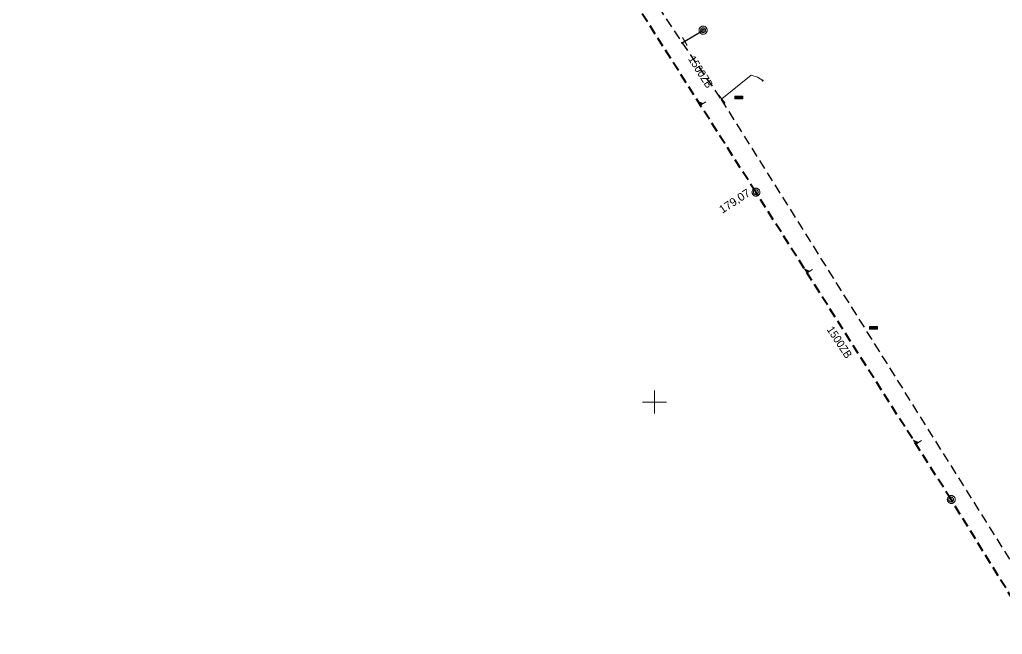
# Model space of a CAD drawing. Extents: x -740851 to -738888, y -1041382 to -1040235.
# Drawn here: x -739579.3 to -739456.5, y -1040929 to -1040852.2 of the extents above; entities that cross this region are included whole.
import ezdxf

# ---------------------------------------------------------------- set-up
doc = ezdxf.new("R2010")
doc.units = 0
doc.header["$LTSCALE"] = 0.4
doc.linetypes.add('MEDIUM_DASHED', pattern=[4.5, 3, -1.5])
for name, color, linetype, lineweight in [('1', 7, 'Continuous', 13), ('18', 7, 'Continuous', 13), ('38', 7, 'Continuous', 13), ('8', 7, 'Continuous', 13)]:
    doc.layers.add(name, color=color, linetype=linetype, lineweight=lineweight)

msp = doc.modelspace()

# ---------------------------------------------------------------- hatches: boundary and pattern name
at = {"layer": '18'}
for points in [[(-739489.96, -1040861.78), (-739489.96, -1040862.12), (-739488.96, -1040862.12), (-739488.96, -1040861.78)], [(-739473.14, -1040890.56), (-739473.14, -1040890.9), (-739472.14, -1040890.9), (-739472.14, -1040890.56)]]:
    msp.add_hatch(color=256, dxfattribs=at).paths.add_polyline_path(points)

# ---------------------------------------------------------------- linework, layer by layer
at = {"layer": '1'}
for p, q in [((-739500, -1040898.571), (-739500, -1040901.429)), ((-739500, -1040898.571), (-739500, -1040901.429)), ((-739501.48, -1040900), (-739498.48, -1040900)), ((-739501.48, -1040900), (-739498.48, -1040900))]:
    msp.add_line(p, q, dxfattribs=at)
at = {"layer": '18', "linetype": 'MEDIUM_DASHED', "lineweight": 40}
for p, q in [((-739487.34, -1040873.78), (-739504.725, -1040846.471)), ((-739462.93, -1040912.16), (-739487.34, -1040873.78)), ((-739433.4, -1040959.96), (-739462.93, -1040912.16))]:
    msp.add_line(p, q, dxfattribs=at)
at = {"layer": '18'}
for p, q in [((-739489.96, -1040861.78), (-739488.96, -1040862.12)), ((-739473.14, -1040890.56), (-739472.14, -1040890.9))]:
    msp.add_line(p, q, dxfattribs=at)
for points in [[(-739489.96, -1040861.78), (-739489.96, -1040862.12), (-739488.96, -1040862.12), (-739488.96, -1040861.78)], [(-739486.81, -1040873.79), (-739486.82, -1040873.74), (-739486.82, -1040873.69), (-739486.84, -1040873.64), (-739486.86, -1040873.59), (-739486.88, -1040873.54), (-739486.91, -1040873.5), (-739486.94, -1040873.46), (-739486.98, -1040873.42), (-739487.02, -1040873.39), (-739487.06, -1040873.36), (-739487.11, -1040873.34), (-739487.16, -1040873.32), (-739487.21, -1040873.3), (-739487.26, -1040873.3), (-739487.31, -1040873.29), (-739487.36, -1040873.3), (-739487.41, -1040873.3), (-739487.46, -1040873.32), (-739487.51, -1040873.34), (-739487.56, -1040873.36), (-739487.6, -1040873.39), (-739487.64, -1040873.42), (-739487.68, -1040873.46), (-739487.71, -1040873.5), (-739487.74, -1040873.54), (-739487.76, -1040873.59), (-739487.78, -1040873.64), (-739487.8, -1040873.69), (-739487.8, -1040873.74), (-739487.81, -1040873.79), (-739487.8, -1040873.84), (-739487.8, -1040873.89), (-739487.78, -1040873.94), (-739487.76, -1040873.99), (-739487.74, -1040874.04), (-739487.71, -1040874.08), (-739487.68, -1040874.12), (-739487.64, -1040874.16), (-739487.6, -1040874.19), (-739487.56, -1040874.22), (-739487.51, -1040874.24), (-739487.46, -1040874.26), (-739487.41, -1040874.28), (-739487.36, -1040874.28), (-739487.31, -1040874.29), (-739487.26, -1040874.28), (-739487.21, -1040874.28), (-739487.16, -1040874.26), (-739487.11, -1040874.24), (-739487.06, -1040874.22), (-739487.02, -1040874.19), (-739486.98, -1040874.16), (-739486.94, -1040874.12), (-739486.91, -1040874.08), (-739486.88, -1040874.04), (-739486.86, -1040873.99), (-739486.84, -1040873.94), (-739486.82, -1040873.89), (-739486.82, -1040873.84)], [(-739487.04, -1040873.78), (-739487.04, -1040873.75), (-739487.046, -1040873.72), (-739487.052, -1040873.69), (-739487.064, -1040873.66), (-739487.082, -1040873.63), (-739487.1, -1040873.606), (-739487.118, -1040873.582), (-739487.142, -1040873.558), (-739487.166, -1040873.54), (-739487.19, -1040873.522), (-739487.22, -1040873.504), (-739487.25, -1040873.492), (-739487.28, -1040873.486), (-739487.31, -1040873.48), (-739487.34, -1040873.48), (-739487.37, -1040873.48), (-739487.4, -1040873.486), (-739487.43, -1040873.492), (-739487.46, -1040873.504), (-739487.49, -1040873.522), (-739487.514, -1040873.54), (-739487.538, -1040873.558), (-739487.562, -1040873.582), (-739487.58, -1040873.606), (-739487.598, -1040873.63), (-739487.616, -1040873.66), (-739487.628, -1040873.69), (-739487.634, -1040873.72), (-739487.64, -1040873.75), (-739487.64, -1040873.78), (-739487.64, -1040873.81), (-739487.634, -1040873.84), (-739487.628, -1040873.87), (-739487.616, -1040873.9), (-739487.598, -1040873.93), (-739487.58, -1040873.954), (-739487.562, -1040873.978), (-739487.538, -1040874.002), (-739487.514, -1040874.02), (-739487.49, -1040874.038), (-739487.46, -1040874.056), (-739487.43, -1040874.068), (-739487.4, -1040874.074), (-739487.37, -1040874.08), (-739487.34, -1040874.08), (-739487.31, -1040874.08), (-739487.28, -1040874.074), (-739487.25, -1040874.068), (-739487.22, -1040874.056), (-739487.19, -1040874.038), (-739487.166, -1040874.02), (-739487.142, -1040874.002), (-739487.118, -1040873.978), (-739487.1, -1040873.954), (-739487.082, -1040873.93), (-739487.064, -1040873.9), (-739487.052, -1040873.87), (-739487.046, -1040873.84), (-739487.04, -1040873.81)], [(-739473.14, -1040890.56), (-739473.14, -1040890.9), (-739472.14, -1040890.9), (-739472.14, -1040890.56)], [(-739462.4, -1040912.17), (-739462.41, -1040912.12), (-739462.41, -1040912.07), (-739462.43, -1040912.02), (-739462.45, -1040911.97), (-739462.47, -1040911.92), (-739462.5, -1040911.88), (-739462.53, -1040911.84), (-739462.57, -1040911.8), (-739462.61, -1040911.77), (-739462.65, -1040911.74), (-739462.7, -1040911.72), (-739462.75, -1040911.7), (-739462.8, -1040911.68), (-739462.85, -1040911.68), (-739462.9, -1040911.67), (-739462.95, -1040911.68), (-739463, -1040911.68), (-739463.05, -1040911.7), (-739463.1, -1040911.72), (-739463.15, -1040911.74), (-739463.19, -1040911.77), (-739463.23, -1040911.8), (-739463.27, -1040911.84), (-739463.3, -1040911.88), (-739463.33, -1040911.92), (-739463.35, -1040911.97), (-739463.37, -1040912.02), (-739463.39, -1040912.07), (-739463.39, -1040912.12), (-739463.4, -1040912.17), (-739463.39, -1040912.22), (-739463.39, -1040912.27), (-739463.37, -1040912.32), (-739463.35, -1040912.37), (-739463.33, -1040912.42), (-739463.3, -1040912.46), (-739463.27, -1040912.5), (-739463.23, -1040912.54), (-739463.19, -1040912.57), (-739463.15, -1040912.6), (-739463.1, -1040912.62), (-739463.05, -1040912.64), (-739463, -1040912.66), (-739462.95, -1040912.66), (-739462.9, -1040912.67), (-739462.85, -1040912.66), (-739462.8, -1040912.66), (-739462.75, -1040912.64), (-739462.7, -1040912.62), (-739462.65, -1040912.6), (-739462.61, -1040912.57), (-739462.57, -1040912.54), (-739462.53, -1040912.5), (-739462.5, -1040912.46), (-739462.47, -1040912.42), (-739462.45, -1040912.37), (-739462.43, -1040912.32), (-739462.41, -1040912.27), (-739462.41, -1040912.22)], [(-739462.63, -1040912.16), (-739462.63, -1040912.13), (-739462.636, -1040912.1), (-739462.642, -1040912.07), (-739462.654, -1040912.04), (-739462.672, -1040912.01), (-739462.69, -1040911.986), (-739462.708, -1040911.962), (-739462.732, -1040911.938), (-739462.756, -1040911.92), (-739462.78, -1040911.902), (-739462.81, -1040911.884), (-739462.84, -1040911.872), (-739462.87, -1040911.866), (-739462.9, -1040911.86), (-739462.93, -1040911.86), (-739462.96, -1040911.86), (-739462.99, -1040911.866), (-739463.02, -1040911.872), (-739463.05, -1040911.884), (-739463.08, -1040911.902), (-739463.104, -1040911.92), (-739463.128, -1040911.938), (-739463.152, -1040911.962), (-739463.17, -1040911.986), (-739463.188, -1040912.01), (-739463.206, -1040912.04), (-739463.218, -1040912.07), (-739463.224, -1040912.1), (-739463.23, -1040912.13), (-739463.23, -1040912.16), (-739463.23, -1040912.19), (-739463.224, -1040912.22), (-739463.218, -1040912.25), (-739463.206, -1040912.28), (-739463.188, -1040912.31), (-739463.17, -1040912.334), (-739463.152, -1040912.358), (-739463.128, -1040912.382), (-739463.104, -1040912.4), (-739463.08, -1040912.418), (-739463.05, -1040912.436), (-739463.02, -1040912.448), (-739462.99, -1040912.454), (-739462.96, -1040912.46), (-739462.93, -1040912.46), (-739462.9, -1040912.46), (-739462.87, -1040912.454), (-739462.84, -1040912.448), (-739462.81, -1040912.436), (-739462.78, -1040912.418), (-739462.756, -1040912.4), (-739462.732, -1040912.382), (-739462.708, -1040912.358), (-739462.69, -1040912.334), (-739462.672, -1040912.31), (-739462.654, -1040912.28), (-739462.642, -1040912.25), (-739462.636, -1040912.22), (-739462.63, -1040912.19)]]:
    msp.add_lwpolyline(points, close=True, dxfattribs=at)
for points in [[(-739493.565, -1040862.48), (-739494.252, -1040862.918), (-739494.565, -1040862.427), (-739493.942, -1040862.721)], [(-739494.034, -1040862.728), (-739494.234, -1040862.856), (-739494.434, -1040862.542), (-739494.032, -1040862.732)], [(-739494.129, -1040862.738), (-739494.229, -1040862.802), (-739494.332, -1040862.641), (-739494.127, -1040862.741)], [(-739480.238, -1040883.423), (-739480.926, -1040883.861), (-739481.238, -1040883.37), (-739480.616, -1040883.663)], [(-739480.708, -1040883.671), (-739480.908, -1040883.798), (-739481.108, -1040883.485), (-739480.706, -1040883.674)], [(-739480.803, -1040883.681), (-739480.903, -1040883.745), (-739481.006, -1040883.584), (-739480.801, -1040883.684)], [(-739466.634, -1040904.813), (-739467.322, -1040905.251), (-739467.634, -1040904.76), (-739467.012, -1040905.054)], [(-739467.104, -1040905.061), (-739467.304, -1040905.189), (-739467.503, -1040904.875), (-739467.101, -1040905.065)], [(-739467.199, -1040905.071), (-739467.299, -1040905.135), (-739467.401, -1040904.974), (-739467.197, -1040905.074)]]:
    msp.add_lwpolyline(points, dxfattribs=at)
at = {"layer": '38'}
msp.add_line((-739491.67, -1040862.2), (-739491.596, -1040862.134), dxfattribs=at)
msp.add_lwpolyline([(-739491.596, -1040862.134), (-739487.9, -1040859.18), (-739487.11, -1040859.4), (-739486.475, -1040859.842)], dxfattribs=at)
at = {"layer": '8'}
for p, q in [((-739495.893, -1040855.46), (-739496.481, -1040854.46)), ((-739496.603, -1040855.171), (-739496.503, -1040855.071)), ((-739496.603, -1040855.071), (-739496.503, -1040855.171)), ((-739496.603, -1040855.071), (-739496.603, -1040855.091)), ((-739496.603, -1040855.071), (-739496.583, -1040855.071)), ((-739496.603, -1040855.171), (-739496.603, -1040855.151)), ((-739496.603, -1040855.171), (-739496.583, -1040855.171)), ((-739496.503, -1040855.071), (-739496.523, -1040855.071)), ((-739496.503, -1040855.171), (-739496.523, -1040855.171)), ((-739496.503, -1040855.071), (-739496.503, -1040855.091)), ((-739496.503, -1040855.171), (-739496.503, -1040855.151)), ((-739486.543, -1040859.855), (-739486.404, -1040859.83)), ((-739486.543, -1040859.855), (-739486.532, -1040859.838)), ((-739486.543, -1040859.855), (-739486.527, -1040859.866)), ((-739486.486, -1040859.772), (-739486.498, -1040859.789)), ((-739486.486, -1040859.772), (-739486.461, -1040859.912)), ((-739486.486, -1040859.772), (-739486.47, -1040859.784)), ((-739486.461, -1040859.912), (-739486.478, -1040859.9)), ((-739486.461, -1040859.912), (-739486.45, -1040859.895)), ((-739486.404, -1040859.83), (-739486.42, -1040859.818)), ((-739486.404, -1040859.83), (-739486.415, -1040859.846)), ((-739491.164, -1040862.674), (-739491.965, -1040861.674))]:
    msp.add_line(p, q, dxfattribs=at)
at = {"layer": '8', "linetype": 'MEDIUM_DASHED', "lineweight": 25}
for points in [[(-739693.286, -1040576.71), (-739686.808, -1040583.233), (-739625.283, -1040665.839), (-739571.664, -1040740.804), (-739523.94, -1040810.745), (-739502.47, -1040846.1), (-739496.554, -1040855.122)], [(-739496.554, -1040855.122), (-739491.67, -1040862.2), (-739374.679, -1041048.562)]]:
    msp.add_lwpolyline(points, dxfattribs=at)
at = {"layer": '8'}
for points in [[(-739493.425, -1040853.55), (-739493.425, -1040853.504), (-739493.425, -1040853.444), (-739493.44, -1040853.398), (-739493.455, -1040853.337), (-739493.486, -1040853.292), (-739493.516, -1040853.247), (-739493.546, -1040853.216), (-739493.592, -1040853.171), (-739493.622, -1040853.141), (-739493.667, -1040853.11), (-739493.713, -1040853.08), (-739493.773, -1040853.065), (-739493.819, -1040853.05), (-739493.879, -1040853.05), (-739493.925, -1040853.05), (-739493.986, -1040853.05), (-739494.031, -1040853.05), (-739494.076, -1040853.065), (-739494.137, -1040853.08), (-739494.183, -1040853.11), (-739494.228, -1040853.141), (-739494.258, -1040853.171), (-739494.304, -1040853.216), (-739494.334, -1040853.247), (-739494.364, -1040853.292), (-739494.395, -1040853.337), (-739494.41, -1040853.398), (-739494.425, -1040853.444), (-739494.425, -1040853.504), (-739494.425, -1040853.55), (-739494.425, -1040853.61), (-739494.425, -1040853.656), (-739494.41, -1040853.701), (-739494.395, -1040853.762), (-739494.364, -1040853.807), (-739494.334, -1040853.853), (-739494.304, -1040853.883), (-739494.258, -1040853.928), (-739494.228, -1040853.959), (-739494.183, -1040853.989), (-739494.137, -1040854.019), (-739494.076, -1040854.034), (-739494.031, -1040854.05), (-739493.986, -1040854.05), (-739493.925, -1040854.05), (-739493.879, -1040854.05), (-739493.819, -1040854.05), (-739493.773, -1040854.034), (-739493.713, -1040854.019), (-739493.667, -1040853.989), (-739493.622, -1040853.959), (-739493.592, -1040853.928), (-739493.546, -1040853.883), (-739493.516, -1040853.853), (-739493.486, -1040853.807), (-739493.455, -1040853.762), (-739493.44, -1040853.701), (-739493.425, -1040853.656), (-739493.425, -1040853.61)], [(-739493.622, -1040853.55), (-739493.622, -1040853.519), (-739493.637, -1040853.489), (-739493.637, -1040853.459), (-739493.652, -1040853.428), (-739493.667, -1040853.398), (-739493.683, -1040853.368), (-739493.698, -1040853.353), (-739493.728, -1040853.322), (-739493.743, -1040853.307), (-739493.773, -1040853.292), (-739493.804, -1040853.277), (-739493.834, -1040853.262), (-739493.864, -1040853.262), (-739493.895, -1040853.247), (-739493.925, -1040853.247), (-739493.955, -1040853.247), (-739493.986, -1040853.262), (-739494.016, -1040853.262), (-739494.046, -1040853.277), (-739494.076, -1040853.292), (-739494.107, -1040853.307), (-739494.122, -1040853.322), (-739494.152, -1040853.353), (-739494.167, -1040853.368), (-739494.183, -1040853.398), (-739494.198, -1040853.428), (-739494.213, -1040853.459), (-739494.213, -1040853.489), (-739494.228, -1040853.519), (-739494.228, -1040853.55), (-739494.228, -1040853.58), (-739494.213, -1040853.61), (-739494.213, -1040853.641), (-739494.198, -1040853.671), (-739494.183, -1040853.701), (-739494.167, -1040853.731), (-739494.152, -1040853.747), (-739494.122, -1040853.777), (-739494.107, -1040853.792), (-739494.076, -1040853.807), (-739494.046, -1040853.822), (-739494.016, -1040853.837), (-739493.986, -1040853.837), (-739493.955, -1040853.853), (-739493.925, -1040853.853), (-739493.895, -1040853.853), (-739493.864, -1040853.837), (-739493.834, -1040853.837), (-739493.804, -1040853.822), (-739493.773, -1040853.807), (-739493.743, -1040853.792), (-739493.728, -1040853.777), (-739493.698, -1040853.747), (-739493.683, -1040853.731), (-739493.667, -1040853.701), (-739493.652, -1040853.671), (-739493.637, -1040853.641), (-739493.637, -1040853.61), (-739493.622, -1040853.58)], [(-739493.789, -1040853.55), (-739493.789, -1040853.534), (-739493.804, -1040853.519), (-739493.804, -1040853.504), (-739493.804, -1040853.489), (-739493.819, -1040853.489), (-739493.819, -1040853.474), (-739493.834, -1040853.459), (-739493.849, -1040853.444), (-739493.864, -1040853.444), (-739493.864, -1040853.428), (-739493.879, -1040853.428), (-739493.895, -1040853.428), (-739493.91, -1040853.413), (-739493.925, -1040853.413), (-739493.94, -1040853.413), (-739493.955, -1040853.428), (-739493.97, -1040853.428), (-739493.986, -1040853.428), (-739493.986, -1040853.444), (-739494.001, -1040853.444), (-739494.016, -1040853.459), (-739494.031, -1040853.474), (-739494.046, -1040853.489), (-739494.046, -1040853.504), (-739494.046, -1040853.519), (-739494.061, -1040853.534), (-739494.061, -1040853.55), (-739494.061, -1040853.565), (-739494.046, -1040853.58), (-739494.046, -1040853.595), (-739494.046, -1040853.61), (-739494.031, -1040853.625), (-739494.016, -1040853.641), (-739494.001, -1040853.656), (-739493.986, -1040853.671), (-739493.97, -1040853.671), (-739493.955, -1040853.671), (-739493.94, -1040853.686), (-739493.925, -1040853.686), (-739493.91, -1040853.686), (-739493.895, -1040853.671), (-739493.879, -1040853.671), (-739493.864, -1040853.671), (-739493.849, -1040853.656), (-739493.834, -1040853.641), (-739493.819, -1040853.625), (-739493.819, -1040853.61), (-739493.804, -1040853.61), (-739493.804, -1040853.595), (-739493.804, -1040853.58), (-739493.789, -1040853.565)], [(-739496.503, -1040855.121), (-739496.503, -1040855.116), (-739496.504, -1040855.111), (-739496.505, -1040855.106), (-739496.507, -1040855.101), (-739496.51, -1040855.096), (-739496.513, -1040855.092), (-739496.516, -1040855.088), (-739496.52, -1040855.084), (-739496.524, -1040855.081), (-739496.528, -1040855.078), (-739496.533, -1040855.075), (-739496.538, -1040855.073), (-739496.543, -1040855.072), (-739496.548, -1040855.071), (-739496.553, -1040855.071), (-739496.558, -1040855.071), (-739496.563, -1040855.072), (-739496.568, -1040855.073), (-739496.573, -1040855.075), (-739496.578, -1040855.078), (-739496.582, -1040855.081), (-739496.586, -1040855.084), (-739496.59, -1040855.088), (-739496.593, -1040855.092), (-739496.596, -1040855.096), (-739496.599, -1040855.101), (-739496.601, -1040855.106), (-739496.602, -1040855.111), (-739496.603, -1040855.116), (-739496.603, -1040855.121), (-739496.603, -1040855.126), (-739496.602, -1040855.131), (-739496.601, -1040855.136), (-739496.599, -1040855.141), (-739496.596, -1040855.146), (-739496.593, -1040855.15), (-739496.59, -1040855.154), (-739496.586, -1040855.158), (-739496.582, -1040855.161), (-739496.578, -1040855.164), (-739496.573, -1040855.167), (-739496.568, -1040855.169), (-739496.563, -1040855.17), (-739496.558, -1040855.171), (-739496.553, -1040855.171), (-739496.548, -1040855.171), (-739496.543, -1040855.17), (-739496.538, -1040855.169), (-739496.533, -1040855.167), (-739496.528, -1040855.164), (-739496.524, -1040855.161), (-739496.52, -1040855.158), (-739496.516, -1040855.154), (-739496.513, -1040855.15), (-739496.51, -1040855.146), (-739496.507, -1040855.141), (-739496.505, -1040855.136), (-739496.504, -1040855.131), (-739496.503, -1040855.126)], [(-739486.433, -1040859.871), (-739486.43, -1040859.867), (-739486.428, -1040859.862), (-739486.426, -1040859.857), (-739486.424, -1040859.852), (-739486.424, -1040859.846), (-739486.424, -1040859.841), (-739486.424, -1040859.836), (-739486.425, -1040859.831), (-739486.427, -1040859.826), (-739486.429, -1040859.821), (-739486.431, -1040859.816), (-739486.434, -1040859.811), (-739486.437, -1040859.808), (-739486.441, -1040859.804), (-739486.445, -1040859.801), (-739486.449, -1040859.798), (-739486.454, -1040859.796), (-739486.458, -1040859.794), (-739486.464, -1040859.793), (-739486.47, -1040859.792), (-739486.475, -1040859.793), (-739486.48, -1040859.793), (-739486.485, -1040859.794), (-739486.49, -1040859.795), (-739486.495, -1040859.797), (-739486.5, -1040859.799), (-739486.504, -1040859.802), (-739486.508, -1040859.806), (-739486.512, -1040859.809), (-739486.515, -1040859.813), (-739486.518, -1040859.818), (-739486.52, -1040859.822), (-739486.522, -1040859.827), (-739486.523, -1040859.832), (-739486.523, -1040859.838), (-739486.523, -1040859.843), (-739486.523, -1040859.848), (-739486.522, -1040859.854), (-739486.52, -1040859.858), (-739486.519, -1040859.863), (-739486.516, -1040859.868), (-739486.513, -1040859.873), (-739486.51, -1040859.877), (-739486.506, -1040859.88), (-739486.502, -1040859.883), (-739486.498, -1040859.886), (-739486.493, -1040859.888), (-739486.489, -1040859.89), (-739486.483, -1040859.891), (-739486.478, -1040859.892), (-739486.473, -1040859.891), (-739486.468, -1040859.891), (-739486.462, -1040859.89), (-739486.457, -1040859.889), (-739486.453, -1040859.887), (-739486.447, -1040859.885), (-739486.443, -1040859.882), (-739486.439, -1040859.878), (-739486.435, -1040859.875)]]:
    msp.add_lwpolyline(points, close=True, dxfattribs=at)
at = {"layer": '8', "lineweight": 25}
msp.add_lwpolyline([(-739496.554, -1040855.122), (-739496.21, -1040854.92), (-739493.94, -1040853.58)], dxfattribs=at)

# ---------------------------------------------------------------- texts
at = {"layer": '18'}
for s, rotation, width, p in [('1500ZB', 302.481, 0.95, (-739495.83, -1040857.152)), ('179,07', 33.235, 1.05, (-739491.523, -1040876.492)), ('1500ZB', 303.457, 0.95, (-739478.513, -1040890.938))]:
    msp.add_text(s, height=1, rotation=rotation, dxfattribs=dict(at, width=width)).set_placement(p)

doc.saveas('drawing.dxf')
